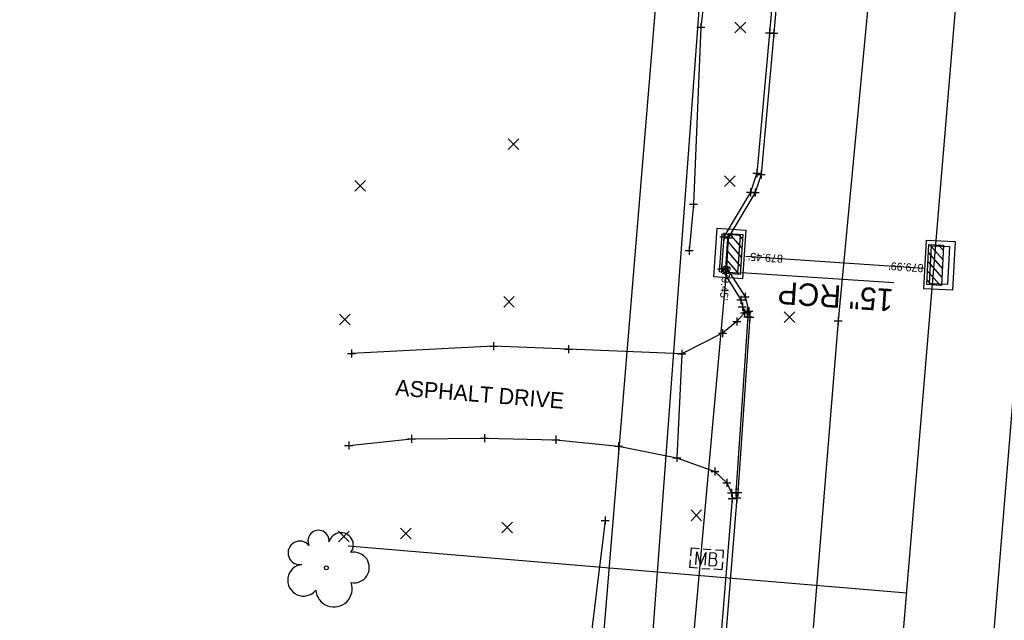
# Model space of a CAD drawing. Extents: x 1380440 to 1381945, y 468756 to 470369.
# Drawn here: x 1381439.7 to 1381562.7, y 469252.2 to 469327.1 of the extents above; entities that cross this region are included whole.
import ezdxf

# ---------------------------------------------------------------- set-up
doc = ezdxf.new("R2010")
doc.units = 0
for name, color, linetype in [('DR_X_Cells', 7, 'Continuous'), ('GE_P_Driveway_CL', 7, 'Continuous'), ('PM_X_CL_Double_Solid', 7, 'Continuous'), ('PV_P_Curb', 7, 'Continuous'), ('PV_P_Curb_Ramp', 7, 'Continuous'), ('PV_P_Joint', 7, 'Continuous'), ('RD_P_Cells', 7, 'Continuous'), ('RW_P_Esmt_TMP', 7, 'Continuous'), ('RW_X_CL', 7, 'Continuous'), ('RW_X_Esmt_SH', 7, 'Continuous'), ('SC_Scratch1', 7, 'Continuous'), ('SC_Scratch10', 7, 'Continuous'), ('SC_Scratch2', 7, 'Continuous'), ('SC_Shading1', 7, 'Continuous'), ('SH_Named_Boundary', 7, 'Continuous'), ('UT_X_Gas', 7, 'Continuous'), ('UT_X_Overhead_Combined', 7, 'Continuous'), ('UT_X_Sanitary_Line', 7, 'Continuous'), ('UT_X_Water', 7, 'Continuous'), ('X-CL', 7, 'Continuous'), ('X-SUBDIVISION', 7, 'Continuous')]:
    doc.layers.add(name, color=color, linetype=linetype)

msp = doc.modelspace()

# ---------------------------------------------------------------- linework, layer by layer
at = {"layer": 'DR_X_Cells'}
for points in [[(1381535.34, 469347.99), (1381535.28, 469347.29), (1381533.36, 469325.49), (1381531.78, 469307.95), (1381530.98, 469305.57), (1381527.65, 469300.02), (1381527.35, 469296.02), (1381529.77, 469292.16), (1381529.97, 469291.26), (1381530.24, 469290.52)], [(1381528.62, 469268.06), (1381528.68, 469267.34), (1381525.83, 469232.26), (1381523.03, 469197.27), (1381522.81, 469196)]]:
    msp.add_lwpolyline(points, dxfattribs=at)
at = {"layer": 'GE_P_Driveway_CL'}
for p, q in [((1381529.05, 469325.46), (1381530.39, 469326.8)), ((1381529.05, 469326.8), (1381530.39, 469325.46)), ((1381500.73, 469310.9), (1381502.06, 469312.23)), ((1381500.73, 469312.23), (1381502.06, 469310.9)), ((1381481.56, 469305.72), (1381482.89, 469307.06)), ((1381481.56, 469307.06), (1381482.89, 469305.72)), ((1381527.74, 469306.31), (1381529.07, 469307.65)), ((1381527.74, 469307.65), (1381529.07, 469306.31)), ((1381500.16, 469291.24), (1381501.49, 469292.58)), ((1381500.16, 469292.58), (1381501.49, 469291.24)), ((1381479.67, 469289.03), (1381481, 469290.37)), ((1381479.67, 469290.37), (1381481, 469289.03)), ((1381535.2, 469289.33), (1381536.53, 469290.66)), ((1381535.2, 469290.66), (1381536.53, 469289.33)), ((1381523.56, 469264.59), (1381524.89, 469265.93)), ((1381523.56, 469265.93), (1381524.89, 469264.59)), ((1381499.92, 469263.07), (1381501.26, 469264.4)), ((1381499.92, 469264.4), (1381501.26, 469263.07)), ((1381479.53, 469261.94), (1381480.86, 469263.28)), ((1381479.53, 469263.28), (1381480.86, 469261.94)), ((1381487.26, 469262.33), (1381488.6, 469263.67)), ((1381487.26, 469263.67), (1381488.6, 469262.33))]:
    msp.add_line(p, q, dxfattribs=at)
at = {"layer": 'PM_X_CL_Double_Solid'}
msp.add_lwpolyline([(1381555.39, 469442.03), (1381550.97, 469391.02), (1381547.28, 469345.9), (1381541.95, 469289.55), (1381537.19, 469231.27), (1381533.05, 469168.09), (1381530.32, 469133.74), (1381523.97, 469065.08), (1381520.12, 469021.37), (1381518.18, 469001.31)], dxfattribs=at)
at = {"layer": 'PV_P_Curb'}
msp.add_lwpolyline([(1381527.14, 469346.36), (1381524.79, 469326.2), (1381523.85, 469304.1), (1381523.31, 469298.29)], dxfattribs=at)
at = {"layer": 'PV_P_Curb_Ramp'}
for p, q in [((1381528.58, 469300.29), (1381528.58, 469300.29)), ((1381554.73, 469298.85), (1381554.73, 469298.85)), ((1381526.62, 469298.05), (1381526.62, 469298.05)), ((1381527.29, 469298), (1381527.29, 469298)), ((1381528.04, 469297.95), (1381528.04, 469297.95)), ((1381528.04, 469297.95), (1381528.04, 469297.95)), ((1381528.41, 469297.92), (1381528.41, 469297.92)), ((1381529.53, 469297.84), (1381529.53, 469297.84)), ((1381530.2, 469297.79), (1381530.2, 469297.79)), ((1381552.81, 469296.58), (1381552.81, 469296.58)), ((1381553.48, 469296.54), (1381553.48, 469296.54)), ((1381554.6, 469296.48), (1381554.6, 469296.48)), ((1381554.97, 469296.46), (1381554.97, 469296.46)), ((1381554.97, 469296.46), (1381554.97, 469296.46)), ((1381555.72, 469296.42), (1381555.72, 469296.42)), ((1381556.39, 469296.38), (1381556.39, 469296.38)), ((1381528.24, 469295.55), (1381528.24, 469295.55)), ((1381554.47, 469294.11), (1381554.47, 469294.11))]:
    msp.add_line(p, q, dxfattribs=at)
at = {"layer": 'PV_P_Joint'}
for p, q in [((1381529.92, 469298.63), (1381528.36, 469300.43)), ((1381530, 469299.76), (1381529.49, 469300.35)), ((1381529.84, 469297.5), (1381528.15, 469299.46)), ((1381553.35, 469299.05), (1381555.01, 469297.2)), ((1381554.49, 469298.99), (1381555.08, 469298.33)), ((1381529.61, 469295.33), (1381527.98, 469297.2)), ((1381529.76, 469296.37), (1381528.06, 469298.33)), ((1381553.22, 469298), (1381554.95, 469296.08)), ((1381528.48, 469295.41), (1381527.9, 469296.08)), ((1381553.16, 469296.88), (1381554.89, 469294.95)), ((1381553.1, 469295.75), (1381554.69, 469293.97)), ((1381553.04, 469294.62), (1381553.56, 469294.03))]:
    msp.add_line(p, q, dxfattribs=at)
for points in [[(1381526.41, 469295.01), (1381526.84, 469301.08), (1381530.42, 469300.83), (1381529.98, 469294.76)], [(1381527.12, 469295.63), (1381527.46, 469300.37), (1381529.7, 469300.21), (1381529.36, 469295.47)], [(1381527.86, 469295.45), (1381528.22, 469300.44), (1381530.04, 469300.31), (1381529.69, 469295.32)], [(1381556.56, 469299.42), (1381556.22, 469293.34), (1381552.64, 469293.54), (1381552.98, 469299.62)], [(1381555.11, 469298.96), (1381554.84, 469293.96), (1381553, 469294.06), (1381553.28, 469299.06)], [(1381555.85, 469298.79), (1381555.59, 469294.05), (1381553.34, 469294.17), (1381553.61, 469298.91)]]:
    msp.add_lwpolyline(points, close=True, dxfattribs=at)
at = {"layer": 'RD_P_Cells'}
for p, q in [((1381525.09, 469261.08), (1381526.09, 469261)), ((1381525.5, 469259.82), (1381525.5, 469259.82)), ((1381524.9, 469258.64), (1381525.9, 469258.57))]:
    msp.add_line(p, q, dxfattribs=at)
for points in [[(1381523.53, 469260.22), (1381523.6, 469261.19), (1381524.57, 469261.12)], [(1381524.15, 469259.12), (1381524.27, 469260.72), (1381524.73, 469259.08), (1381525.4, 469260.63), (1381525.28, 469259.04)], [(1381526.53, 469259.81), (1381526.6, 469259.87), (1381526.64, 469259.91), (1381526.67, 469259.94), (1381526.68, 469259.97), (1381526.71, 469260.02), (1381526.72, 469260.05), (1381526.76, 469260.14), (1381526.76, 469260.18), (1381526.76, 469260.23), (1381526.76, 469260.3), (1381526.74, 469260.37), (1381526.7, 469260.42), (1381526.64, 469260.47), (1381526.59, 469260.5), (1381526.57, 469260.52), (1381526.51, 469260.55), (1381525.89, 469260.59), (1381525.77, 469259), (1381526.46, 469258.95), (1381526.56, 469258.99), (1381526.64, 469259.05), (1381526.71, 469259.14), (1381526.75, 469259.25), (1381526.77, 469259.37), (1381526.78, 469259.44), (1381526.76, 469259.52), (1381526.72, 469259.64), (1381526.66, 469259.72), (1381526.53, 469259.81), (1381525.84, 469259.87)], [(1381526.6, 469260.96), (1381527.59, 469260.89), (1381527.52, 469259.92)], [(1381524.39, 469258.68), (1381523.42, 469258.75), (1381523.49, 469259.72)], [(1381527.48, 469259.42), (1381527.41, 469258.45), (1381526.42, 469258.53)]]:
    msp.add_lwpolyline(points, dxfattribs=at)
at = {"layer": 'RW_P_Esmt_TMP'}
msp.add_lwpolyline([(1381541, 469413.22), (1381539.53, 469394.02), (1381539.58, 469392.93), (1381538.09, 469374.98), (1381538.03, 469373.76), (1381535.92, 469348.28), (1381535.79, 469347.09), (1381533.91, 469325.42), (1381532.32, 469307.8), (1381531.56, 469305.55), (1381528.19, 469299.9), (1381527.99, 469296.13), (1381530.34, 469292.53), (1381530.8, 469290.75), (1381530.92, 469290), (1381529.4, 469268.09), (1381529.3, 469267.44), (1381526.47, 469232.31)], dxfattribs=at)
at = {"layer": 'RW_X_CL'}
msp.add_line((1381529.85, 469295.58), (1381548.9, 469294.3), dxfattribs=at)
at = {"layer": 'RW_X_Esmt_SH'}
for points in [[(1381530.24, 469290.52), (1381529.29, 469289.43), (1381527.48, 469288), (1381522.43, 469285.41), (1381521.8, 469272.45), (1381526.53, 469270.72), (1381528.04, 469269.3), (1381528.62, 469268.06)], [(1381530.24, 469290.52), (1381530.57, 469290.63), (1381530.67, 469290.02), (1381529.16, 469268.09), (1381528.62, 469268.06)], [(1381522.43, 469285.41), (1381508.26, 469285.98), (1381498.91, 469286.38), (1381481.14, 469285.44)], [(1381480.8, 469273.97), (1381488.65, 469274.82), (1381497.76, 469274.89), (1381506.68, 469274.7), (1381514.52, 469273.9), (1381521.8, 469272.45)]]:
    msp.add_lwpolyline(points, dxfattribs=at)
at = {"layer": 'SC_Scratch10'}
msp.add_circle((1381478.01, 469258.7), 0.24, dxfattribs=at)
for centre, radius, start, end in [((1381477.03, 469262.07), 1.32, 354.0047, 205.9741), ((1381479.84, 469261.53), 1.55, 323.83, 165.0376), ((1381474.7, 469260.57), 1.47, 39.0625, 279.5412), ((1381481.47, 469258.74), 1.91, 259.1453, 101.4596), ((1381475.16, 469257.15), 1.97, 96.1722, 320.5737), ((1381478.96, 469256.1), 2.28, 184.9476, 19.4572)]:
    msp.add_arc(centre, radius, start, end, dxfattribs=at)
at = {"layer": 'SC_Scratch2'}
msp.add_lwpolyline([(1381512.83, 469264.6), (1381509.11, 469234.08), (1381505.62, 469200.41)], dxfattribs=at)
at = {"layer": 'SC_Shading1'}
msp.add_lwpolyline([(1381555.39, 469442.03), (1381550.97, 469391.02), (1381547.28, 469345.9), (1381541.95, 469289.55), (1381537.19, 469231.27), (1381533.05, 469168.09), (1381530.32, 469133.74), (1381523.97, 469065.08), (1381520.12, 469021.37), (1381518.18, 469001.31)], dxfattribs=at)
at = {"layer": 'SH_Named_Boundary'}
for p, q in [((1381524.29, 469326.2), (1381525.29, 469326.2)), ((1381524.79, 469326.7), (1381524.79, 469325.7)), ((1381524.79, 469326.2), (1381524.79, 469326.2)), ((1381532.86, 469325.49), (1381533.86, 469325.49)), ((1381533.36, 469325.99), (1381533.36, 469324.99)), ((1381533.36, 469325.49), (1381533.36, 469325.49)), ((1381533.91, 469325.92), (1381533.91, 469324.92)), ((1381533.41, 469325.42), (1381534.41, 469325.42)), ((1381533.91, 469325.42), (1381533.91, 469325.42)), ((1381531.78, 469308.45), (1381531.78, 469307.45)), ((1381532.32, 469308.3), (1381532.32, 469307.3)), ((1381531.28, 469307.95), (1381532.28, 469307.95)), ((1381531.78, 469307.95), (1381531.78, 469307.95)), ((1381531.82, 469307.8), (1381532.82, 469307.8)), ((1381532.32, 469307.8), (1381532.32, 469307.8)), ((1381530.98, 469306.07), (1381530.98, 469305.07)), ((1381531.56, 469306.05), (1381531.56, 469305.05)), ((1381523.85, 469304.6), (1381523.85, 469303.6)), ((1381530.48, 469305.57), (1381531.48, 469305.57)), ((1381530.98, 469305.57), (1381530.98, 469305.57)), ((1381531.06, 469305.55), (1381532.06, 469305.55)), ((1381531.56, 469305.55), (1381531.56, 469305.55)), ((1381523.35, 469304.1), (1381524.35, 469304.1)), ((1381523.85, 469304.1), (1381523.85, 469304.1)), ((1381527.15, 469300.02), (1381528.15, 469300.02)), ((1381527.65, 469300.52), (1381527.65, 469299.52)), ((1381527.65, 469300.02), (1381527.65, 469300.02)), ((1381527.69, 469299.9), (1381528.69, 469299.9)), ((1381528.19, 469300.4), (1381528.19, 469299.4)), ((1381528.19, 469299.9), (1381528.19, 469299.9)), ((1381523.31, 469298.79), (1381523.31, 469297.79)), ((1381522.81, 469298.29), (1381523.81, 469298.29)), ((1381523.31, 469298.29), (1381523.31, 469298.29)), ((1381526.85, 469296.02), (1381527.85, 469296.02)), ((1381527.35, 469296.52), (1381527.35, 469295.52)), ((1381527.35, 469296.02), (1381527.35, 469296.02)), ((1381527.49, 469296.13), (1381528.49, 469296.13)), ((1381527.99, 469296.63), (1381527.99, 469295.63)), ((1381527.99, 469296.13), (1381527.99, 469296.13)), ((1381529.77, 469292.66), (1381529.77, 469291.66)), ((1381529.84, 469292.53), (1381530.84, 469292.53)), ((1381530.34, 469293.03), (1381530.34, 469292.03)), ((1381530.34, 469292.53), (1381530.34, 469292.53)), ((1381529.27, 469292.16), (1381530.27, 469292.16)), ((1381529.47, 469291.26), (1381530.47, 469291.26)), ((1381529.77, 469292.16), (1381529.77, 469292.16)), ((1381529.97, 469291.76), (1381529.97, 469290.76)), ((1381529.97, 469291.26), (1381529.97, 469291.26)), ((1381530.57, 469291.13), (1381530.57, 469290.13)), ((1381530.8, 469291.25), (1381530.8, 469290.25)), ((1381529.29, 469289.93), (1381529.29, 469288.93)), ((1381529.74, 469290.52), (1381530.74, 469290.52)), ((1381529.74, 469290.52), (1381530.74, 469290.52)), ((1381529.74, 469290.52), (1381530.74, 469290.52)), ((1381530.07, 469290.63), (1381531.07, 469290.63)), ((1381530.17, 469290.02), (1381531.17, 469290.02)), ((1381530.24, 469291.02), (1381530.24, 469290.02)), ((1381530.24, 469291.02), (1381530.24, 469290.02)), ((1381530.24, 469291.02), (1381530.24, 469290.02)), ((1381530.24, 469290.52), (1381530.24, 469290.52)), ((1381530.24, 469290.52), (1381530.24, 469290.52)), ((1381530.24, 469290.52), (1381530.24, 469290.52)), ((1381530.3, 469290.75), (1381531.3, 469290.75)), ((1381530.42, 469290), (1381531.42, 469290)), ((1381530.57, 469290.63), (1381530.57, 469290.63)), ((1381530.67, 469290.52), (1381530.67, 469289.52)), ((1381530.67, 469290.02), (1381530.67, 469290.02)), ((1381530.8, 469290.75), (1381530.8, 469290.75)), ((1381530.92, 469290.5), (1381530.92, 469289.5)), ((1381530.92, 469290), (1381530.92, 469290)), ((1381541.95, 469290.05), (1381541.95, 469289.05)), ((1381528.79, 469289.43), (1381529.79, 469289.43)), ((1381529.29, 469289.43), (1381529.29, 469289.43)), ((1381541.45, 469289.55), (1381542.45, 469289.55)), ((1381541.95, 469289.55), (1381541.95, 469289.55)), ((1381526.98, 469288), (1381527.98, 469288)), ((1381527.48, 469288.5), (1381527.48, 469287.5)), ((1381527.48, 469288), (1381527.48, 469288)), ((1381498.41, 469286.38), (1381499.41, 469286.38)), ((1381498.91, 469286.88), (1381498.91, 469285.88)), ((1381498.91, 469286.38), (1381498.91, 469286.38)), ((1381508.26, 469286.48), (1381508.26, 469285.48)), ((1381480.64, 469285.44), (1381481.64, 469285.44)), ((1381481.14, 469285.94), (1381481.14, 469284.94)), ((1381481.14, 469285.44), (1381481.14, 469285.44)), ((1381507.76, 469285.98), (1381508.76, 469285.98)), ((1381508.26, 469285.98), (1381508.26, 469285.98)), ((1381521.93, 469285.41), (1381522.93, 469285.41)), ((1381521.93, 469285.41), (1381522.93, 469285.41)), ((1381522.43, 469285.91), (1381522.43, 469284.91)), ((1381522.43, 469285.91), (1381522.43, 469284.91)), ((1381522.43, 469285.41), (1381522.43, 469285.41)), ((1381522.43, 469285.41), (1381522.43, 469285.41)), ((1381488.65, 469275.32), (1381488.65, 469274.32)), ((1381497.76, 469275.39), (1381497.76, 469274.39)), ((1381506.68, 469275.2), (1381506.68, 469274.2)), ((1381480.3, 469273.97), (1381481.3, 469273.97)), ((1381480.8, 469274.47), (1381480.8, 469273.47)), ((1381480.8, 469273.97), (1381480.8, 469273.97)), ((1381488.15, 469274.82), (1381489.15, 469274.82)), ((1381488.65, 469274.82), (1381488.65, 469274.82)), ((1381497.26, 469274.89), (1381498.26, 469274.89)), ((1381497.76, 469274.89), (1381497.76, 469274.89)), ((1381506.18, 469274.7), (1381507.18, 469274.7)), ((1381506.68, 469274.7), (1381506.68, 469274.7)), ((1381514.02, 469273.9), (1381515.02, 469273.9)), ((1381514.52, 469274.4), (1381514.52, 469273.4)), ((1381514.52, 469273.9), (1381514.52, 469273.9)), ((1381521.8, 469272.95), (1381521.8, 469271.95)), ((1381521.8, 469272.95), (1381521.8, 469271.95)), ((1381521.3, 469272.45), (1381522.3, 469272.45)), ((1381521.3, 469272.45), (1381522.3, 469272.45)), ((1381521.8, 469272.45), (1381521.8, 469272.45)), ((1381521.8, 469272.45), (1381521.8, 469272.45)), ((1381526.03, 469270.72), (1381527.03, 469270.72)), ((1381526.53, 469271.22), (1381526.53, 469270.22)), ((1381526.53, 469270.72), (1381526.53, 469270.72)), ((1381527.54, 469269.3), (1381528.54, 469269.3)), ((1381528.04, 469269.8), (1381528.04, 469268.8)), ((1381528.04, 469269.3), (1381528.04, 469269.3)), ((1381528.12, 469268.06), (1381529.12, 469268.06)), ((1381528.12, 469268.06), (1381529.12, 469268.06)), ((1381528.12, 469268.06), (1381529.12, 469268.06)), ((1381528.12, 469268.06), (1381529.12, 469268.06)), ((1381528.62, 469268.56), (1381528.62, 469267.56)), ((1381528.62, 469268.56), (1381528.62, 469267.56)), ((1381528.62, 469268.56), (1381528.62, 469267.56)), ((1381528.62, 469268.56), (1381528.62, 469267.56)), ((1381528.62, 469268.06), (1381528.62, 469268.06)), ((1381528.62, 469268.06), (1381528.62, 469268.06)), ((1381528.62, 469268.06), (1381528.62, 469268.06)), ((1381528.62, 469268.06), (1381528.62, 469268.06)), ((1381528.66, 469268.09), (1381529.66, 469268.09)), ((1381528.68, 469267.84), (1381528.68, 469266.84)), ((1381528.9, 469268.09), (1381529.9, 469268.09)), ((1381529.16, 469268.59), (1381529.16, 469267.59)), ((1381529.16, 469268.09), (1381529.16, 469268.09)), ((1381529.3, 469267.94), (1381529.3, 469266.94)), ((1381529.4, 469268.59), (1381529.4, 469267.59)), ((1381529.4, 469268.09), (1381529.4, 469268.09)), ((1381528.18, 469267.34), (1381529.18, 469267.34)), ((1381528.68, 469267.34), (1381528.68, 469267.34)), ((1381528.8, 469267.44), (1381529.8, 469267.44)), ((1381529.3, 469267.44), (1381529.3, 469267.44)), ((1381512.33, 469264.6), (1381513.33, 469264.6)), ((1381512.83, 469265.1), (1381512.83, 469264.1)), ((1381512.83, 469264.6), (1381512.83, 469264.6))]:
    msp.add_line(p, q, dxfattribs=at)
at = {"layer": 'UT_X_Gas'}
msp.add_lwpolyline([(1381485.9, 468926.41), (1381594.27, 470237.89), (1380558, 470279.29)], dxfattribs=at)
at = {"layer": 'UT_X_Overhead_Combined'}
msp.add_lwpolyline([(1381540.8, 469054.26), (1381515.28, 469203.1), (1381529.17, 469390.12), (1381543.86, 469565.78), (1381559.77, 469757.41), (1381571.97, 469887.64), (1381581.26, 470018.2), (1381595.79, 470220.83), (1381665.56, 470247.4)], dxfattribs=at)
at = {"layer": 'UT_X_Sanitary_Line'}
msp.add_line((1381552.86, 469145.47), (1381576.01, 469430.09), dxfattribs=at)
at = {"layer": 'UT_X_Water'}
for p, q in [((1381545.41, 469194.71), (1381630.26, 470209.69)), ((1381550.5, 469255.55), (1381480.75, 469261.42))]:
    msp.add_line(p, q, dxfattribs=at)
at = {"layer": 'X-CL'}
for p, q in [((1381552.6, 469296.08), (1381530.41, 469297.57)), ((1381528.04, 469296.45), (1381500.71, 468992.41))]:
    msp.add_line(p, q, dxfattribs=at)

# ---------------------------------------------------------------- texts
at = {"layer": 'RW_X_CL'}
msp.add_text('15" RCP', height=2.8, rotation=176.166, dxfattribs=at).set_placement((1381548.9, 469293.48))
at = {"layer": 'SC_Scratch1'}
for s, rotation, p in [("879.45'", 176.166, (1381535.07, 469297.76)), ("879.45'", 264.8634, (1381527.54, 469296.49)), ("879.99'", 176.166, (1381552.63, 469296.58))]:
    msp.add_text(s, height=1, rotation=rotation, dxfattribs=at).set_placement(p)
at = {"layer": 'X-SUBDIVISION'}
msp.add_text('ASPHALT DRIVE', height=2, rotation=355.4428, dxfattribs=at).set_placement((1381486.58, 469280.23))

doc.saveas('drawing.dxf')
